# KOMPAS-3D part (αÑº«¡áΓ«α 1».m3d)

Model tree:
1. Эскиз:1
2. Операция выдавливания:1
     Толщина стенки 1 = 2; Толщина стенки 2 = 8; Расстояние 1 = 1
3. Эскиз:3
4. Операция выдавливания:2
     Толщина стенки 1 = 2; Толщина стенки 2 = 6; Расстояние 1 = 5
5. Эскиз:4
6. Операция выдавливания:3
     Толщина стенки 1 = 2; Толщина стенки 2 = 6; Расстояние 1 = 1
7. Эскиз:5
8. Эскиз:6
9. Операция выдавливания:4
     Толщина стенки 1 = 2; Толщина стенки 2 = 2.5; Расстояние 1 = 50
10. Эскиз:7
11. Вырезать элемент выдавливания:1
     Толщина стенки 2 = 1.5; Расстояние 1 = 40
12. Эскиз:8
13. Операция выдавливания:5
     Толщина стенки 1 = 2; Толщина стенки 2 = 2.5; Расстояние 1 = 50
14. Эскиз:9
15. Вырезать элемент выдавливания:2
     Толщина стенки 2 = 1.5; Расстояние 1 = 40
16. Эскиз:10
17. Операция выдавливания:6
     Толщина стенки 1 = 2; Толщина стенки 2 = 2.5; Расстояние 1 = 10
18. Эскиз:11
19. Операция выдавливания:7
     Толщина стенки 1 = 2; Толщина стенки 2 = 6; Расстояние 1 = 1
20. Эскиз:12
21. Операция выдавливания:8
     Толщина стенки 1 = 2; Толщина стенки 2 = 6; Расстояние 1 = 5
22. Эскиз:13
23. Операция выдавливания:9
     Толщина стенки 1 = 2; Толщина стенки 2 = 8; Расстояние 1 = 1
24. Эскиз:14
25. Вырезать элемент выдавливания:3
     Толщина стенки 2 = 1.5; Расстояние 1 = 23
26. Эскиз:15
27. Вырезать элемент выдавливания:4
     Толщина стенки 2 = 1.5; Расстояние 1 = 1
28. Эскиз:16
29. Вырезать элемент выдавливания:5
     Расстояние 1 = 150
30. Эскиз:17
31. Операция выдавливания:10
     Толщина стенки 1 = 8; Толщина стенки 2 = 8; Расстояние 1 = 10; Расстояние 2 = 0.4
